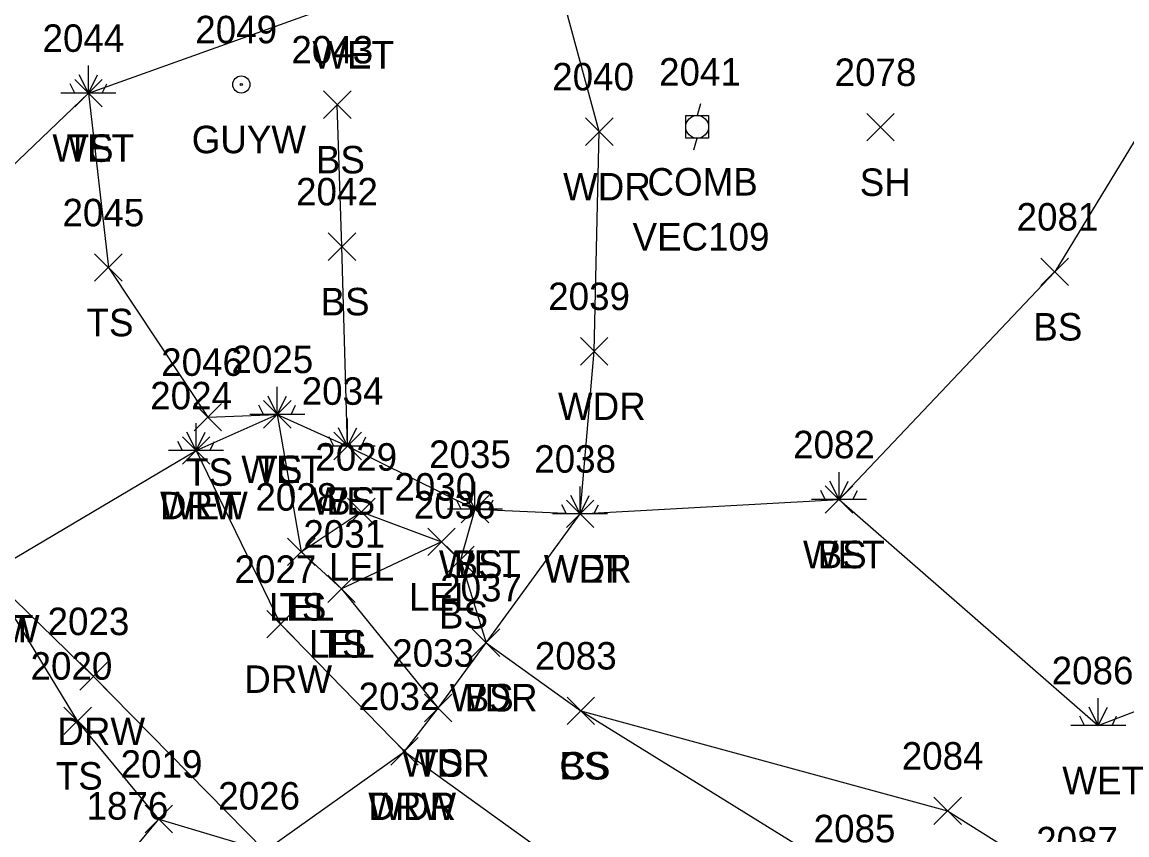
# Model space of a CAD drawing. Extents: x 1512665 to 1513714, y 110636 to 112816.
# Drawn here: x 1512834.1 to 1512914.5, y 110931.3 to 110990.4 of the extents above; entities that cross this region are included whole.
import ezdxf

# ---------------------------------------------------------------- set-up
doc = ezdxf.new("R2010")
doc.units = 0
for name, color, linetype in [('L_A', 7, 'Continuous'), ('L_I', 7, 'Continuous'), ('L_TIC', 7, 'Continuous'), ('LARO', 7, 'Continuous'), ('LAWA', 7, 'Continuous'), ('LELB', 7, 'Continuous'), ('LWET', 7, 'Continuous'), ('R_A', 7, 'Continuous'), ('R_I', 7, 'Continuous'), ('R_TIC', 7, 'Continuous'), ('RDW', 7, 'Continuous'), ('U_A', 7, 'Continuous'), ('U_C', 7, 'Continuous'), ('U_I', 7, 'Continuous'), ('UP', 7, 'Continuous'), ('UPGW', 7, 'Continuous')]:
    doc.layers.add(name, color=color, linetype=linetype)

msp = doc.modelspace()

# ---------------------------------------------------------------- linework, layer by layer
at = {"layer": 'L_TIC'}
for points in [[(1512837.974, 110984.231), (1512839.974, 110986.231)], [(1512839.974, 110984.231), (1512837.974, 110986.231)], [(1512856.074, 110983.389), (1512858.074, 110985.389)], [(1512858.074, 110983.389), (1512856.074, 110985.389)], [(1512875.134, 110981.426), (1512877.134, 110983.426)], [(1512877.134, 110981.426), (1512875.134, 110983.426)], [(1512895.59, 110981.748), (1512897.59, 110983.748)], [(1512897.59, 110981.748), (1512895.59, 110983.748)], [(1512856.414, 110973.06), (1512858.414, 110975.06)], [(1512858.414, 110973.06), (1512856.414, 110975.06)], [(1512839.423, 110971.538), (1512841.423, 110973.538)], [(1512841.423, 110971.538), (1512839.423, 110973.538)], [(1512908.261, 110971.229), (1512910.261, 110973.229)], [(1512910.261, 110971.229), (1512908.261, 110973.229)], [(1512874.763, 110965.444), (1512876.763, 110967.444)], [(1512876.763, 110965.444), (1512874.763, 110967.444)], [(1512846.659, 110960.657), (1512848.659, 110962.657)], [(1512848.659, 110960.657), (1512846.659, 110962.657)], [(1512851.714, 110960.858), (1512853.714, 110962.858)], [(1512853.714, 110960.858), (1512851.714, 110962.858)], [(1512856.825, 110958.552), (1512858.825, 110960.552)], [(1512858.825, 110958.552), (1512856.825, 110960.552)], [(1512892.574, 110954.661), (1512894.574, 110956.661)], [(1512894.574, 110954.661), (1512892.574, 110956.661)], [(1512857.822, 110953.761), (1512859.822, 110955.761)], [(1512859.822, 110953.761), (1512857.822, 110955.761)], [(1512866.091, 110953.959), (1512868.091, 110955.959)], [(1512868.091, 110953.959), (1512866.091, 110955.959)], [(1512873.74, 110953.614), (1512875.74, 110955.614)], [(1512875.74, 110953.614), (1512873.74, 110955.614)], [(1512863.653, 110951.582), (1512865.653, 110953.582)], [(1512865.653, 110951.582), (1512863.653, 110953.582)], [(1512853.458, 110950.85), (1512855.458, 110952.85)], [(1512855.458, 110950.85), (1512853.458, 110952.85)], [(1512853.458, 110950.85), (1512855.458, 110952.85)], [(1512855.458, 110950.85), (1512853.458, 110952.85)], [(1512865.028, 110950.273), (1512867.028, 110952.273)], [(1512867.028, 110950.273), (1512865.028, 110952.273)], [(1512856.381, 110948.159), (1512858.381, 110950.159)], [(1512858.381, 110948.159), (1512856.381, 110950.159)], [(1512856.381, 110948.159), (1512858.381, 110950.159)], [(1512858.381, 110948.159), (1512856.381, 110950.159)], [(1512866.897, 110944.243), (1512868.897, 110946.243)], [(1512868.897, 110944.243), (1512866.897, 110946.243)], [(1512866.897, 110944.243), (1512868.897, 110946.243)], [(1512868.897, 110944.243), (1512866.897, 110946.243)], [(1512863.411, 110939.492), (1512865.411, 110941.492)], [(1512865.411, 110939.492), (1512863.411, 110941.492)], [(1512863.411, 110939.492), (1512865.411, 110941.492)], [(1512865.411, 110939.492), (1512863.411, 110941.492)], [(1512873.787, 110939.291), (1512875.787, 110941.291)], [(1512875.787, 110939.291), (1512873.787, 110941.291)], [(1512873.787, 110939.291), (1512875.787, 110941.291)], [(1512875.787, 110939.291), (1512873.787, 110941.291)], [(1512837.189, 110938.553), (1512839.189, 110940.553)], [(1512839.189, 110938.553), (1512837.189, 110940.553)], [(1512860.965, 110936.336), (1512862.965, 110938.336)], [(1512862.965, 110936.336), (1512860.965, 110938.336)], [(1512900.473, 110932.009), (1512902.473, 110934.009)], [(1512902.473, 110932.009), (1512900.473, 110934.009)], [(1512843.095, 110931.413), (1512845.095, 110933.413)], [(1512845.095, 110931.413), (1512843.095, 110933.413)], [(1512843.095, 110931.413), (1512845.095, 110933.413)], [(1512845.095, 110931.413), (1512843.095, 110933.413)]]:
    msp.add_lwpolyline(points, dxfattribs=at)
at = {"layer": 'LARO'}
msp.add_lwpolyline([(1512854.458, 110951.85), (1512858.822, 110954.761), (1512864.653, 110952.582), (1512857.381, 110949.159)], dxfattribs=at)
at = {"layer": 'LAWA'}
msp.add_lwpolyline([(1512760.327, 110918.9), (1512772.715, 110925.351), (1512775.007, 110936.434), (1512792.554, 110938.683), (1512803.23, 110932.988), (1512815.948, 110931.191), (1512841.584, 110929.37), (1512844.095, 110932.413), (1512851.809, 110930.104), (1512861.965, 110937.336), (1512864.411, 110940.492), (1512867.897, 110945.243), (1512874.74, 110954.614), (1512875.763, 110966.444), (1512876.134, 110982.426), (1512872.076, 110997.369), (1512855.488, 111002.566), (1512840.685, 111007.355)], dxfattribs=at)
at = {"layer": 'LELB'}
for points in [[(1512880.997, 111069.891), (1512889.284, 111054.318), (1512904.053, 111034.187), (1512918.024, 111009.828), (1512920.134, 110990.073), (1512909.261, 110972.229), (1512893.574, 110955.661)], [(1512838.974, 110985.231), (1512840.423, 110972.538), (1512847.659, 110961.657)], [(1512857.825, 110959.552), (1512857.414, 110974.06), (1512857.074, 110984.389)], [(1512847.659, 110961.657), (1512852.714, 110961.858)], [(1512852.714, 110961.858), (1512854.458, 110951.85), (1512857.381, 110949.159), (1512864.411, 110940.492)], [(1512867.091, 110954.959), (1512866.028, 110951.273), (1512867.897, 110945.243), (1512874.787, 110940.291), (1512895.063, 110927.72), (1512902.508, 110913.749), (1512928.484, 110897.044), (1512945.574, 110871.654), (1512953.444, 110855.33), (1512967.722, 110840.945), (1512974.771, 110829.535), (1512966.081, 110822.54), (1512959.925, 110816.123)], [(1512844.095, 110932.413), (1512838.189, 110939.553), (1512831.666, 110950.261)], [(1512874.787, 110940.291), (1512901.473, 110933.009), (1512911.254, 110926.844), (1512935.137, 110909.972), (1512951.516, 110893.128), (1512955.624, 110874.23), (1512953.444, 110855.33)]]:
    msp.add_lwpolyline(points, dxfattribs=at)
at = {"layer": 'LWET'}
for p, q in [((1512838.974, 110985.231), (1512838.974, 110987.231)), ((1512837.974, 110985.231), (1512837.641, 110985.897)), ((1512838.974, 110985.231), (1512838.307, 110986.564)), ((1512838.974, 110985.231), (1512839.641, 110986.564)), ((1512839.974, 110985.231), (1512840.307, 110985.897)), ((1512840.974, 110985.231), (1512836.974, 110985.231)), ((1512852.714, 110961.858), (1512852.714, 110963.858)), ((1512851.714, 110961.858), (1512851.38, 110962.524)), ((1512852.714, 110961.858), (1512852.047, 110963.191)), ((1512852.714, 110961.858), (1512853.38, 110963.191)), ((1512853.714, 110961.858), (1512854.047, 110962.524)), ((1512854.714, 110961.858), (1512850.714, 110961.858)), ((1512846.807, 110959.221), (1512846.807, 110961.221)), ((1512857.825, 110959.552), (1512857.825, 110961.552)), ((1512846.807, 110959.221), (1512846.14, 110960.554)), ((1512846.807, 110959.221), (1512847.473, 110960.554)), ((1512856.825, 110959.552), (1512856.492, 110960.219)), ((1512857.825, 110959.552), (1512857.159, 110960.886)), ((1512857.825, 110959.552), (1512858.492, 110960.886)), ((1512858.825, 110959.552), (1512859.159, 110960.219)), ((1512845.807, 110959.221), (1512845.473, 110959.887)), ((1512847.807, 110959.221), (1512848.14, 110959.887)), ((1512859.825, 110959.552), (1512855.825, 110959.552)), ((1512848.807, 110959.221), (1512844.807, 110959.221)), ((1512867.091, 110954.959), (1512867.091, 110956.959)), ((1512893.574, 110955.661), (1512892.907, 110956.995)), ((1512893.574, 110955.661), (1512893.574, 110957.661)), ((1512893.574, 110955.661), (1512894.24, 110956.995)), ((1512867.091, 110954.959), (1512866.424, 110956.292)), ((1512867.091, 110954.959), (1512867.757, 110956.292)), ((1512874.74, 110954.614), (1512874.74, 110956.614)), ((1512892.574, 110955.661), (1512892.24, 110956.328)), ((1512894.574, 110955.661), (1512894.907, 110956.328)), ((1512866.091, 110954.959), (1512865.757, 110955.626)), ((1512868.091, 110954.959), (1512868.424, 110955.626)), ((1512874.74, 110954.614), (1512874.074, 110955.948)), ((1512874.74, 110954.614), (1512875.407, 110955.948)), ((1512895.574, 110955.661), (1512891.574, 110955.661)), ((1512869.091, 110954.959), (1512865.091, 110954.959)), ((1512876.74, 110954.614), (1512872.74, 110954.614)), ((1512873.74, 110954.614), (1512873.407, 110955.281)), ((1512875.74, 110954.614), (1512876.074, 110955.281)), ((1512912.432, 110939.219), (1512912.432, 110941.219)), ((1512912.432, 110939.219), (1512911.765, 110940.553)), ((1512912.432, 110939.219), (1512913.099, 110940.553)), ((1512914.432, 110939.219), (1512910.432, 110939.219)), ((1512911.432, 110939.219), (1512911.099, 110939.886)), ((1512913.432, 110939.219), (1512913.765, 110939.886))]:
    msp.add_line(p, q, dxfattribs=at)
for points in [[(1512827.592, 110974.325), (1512838.974, 110985.231), (1512857.888, 110992.021), (1512872.076, 110997.369), (1512896.468, 110995.837), (1512920.134, 110990.073), (1512933.522, 110995.148), (1512956.567, 110999.31), (1512966.081, 111012.924), (1512978.758, 111015.543)], [(1512828.676, 110967.967), (1512826.314, 110951.237), (1512831.666, 110950.261), (1512846.807, 110959.221), (1512852.714, 110961.858), (1512857.825, 110959.552), (1512867.091, 110954.959), (1512874.74, 110954.614), (1512893.574, 110955.661), (1512912.432, 110939.219), (1512933.394, 110947.269), (1512941.465, 110952.585), (1512958.813, 110964.455), (1512973.513, 110967.07), (1512985.654, 110971.062)]]:
    msp.add_lwpolyline(points, dxfattribs=at)
at = {"layer": 'R_TIC'}
for points in [[(1512845.807, 110958.221), (1512847.807, 110960.221)], [(1512847.807, 110958.221), (1512845.807, 110960.221)], [(1512851.941, 110945.592), (1512853.941, 110947.592)], [(1512853.941, 110945.592), (1512851.941, 110947.592)], [(1512838.34, 110941.793), (1512840.34, 110943.793)], [(1512840.34, 110941.793), (1512838.34, 110943.793)], [(1512860.965, 110936.336), (1512862.965, 110938.336)], [(1512862.965, 110936.336), (1512860.965, 110938.336)]]:
    msp.add_lwpolyline(points, dxfattribs=at)
at = {"layer": 'RDW'}
for points in [[(1512846.807, 110959.221), (1512852.941, 110946.592), (1512861.965, 110937.336), (1512883.211, 110922.012), (1512899.968, 110905.165), (1512926.485, 110873.446), (1512935.332, 110863.205), (1512946.848, 110850.628), (1512960.543, 110832.025), (1512963.612, 110826.617), (1512966.081, 110822.54), (1512965.912, 110813.145), (1512965.768, 110809.049), (1512964.105, 110806.986), (1512962.879, 110803.833)], [(1512831.666, 110950.261), (1512839.34, 110942.793), (1512851.809, 110930.104), (1512872.871, 110913.575), (1512891.99, 110892.675), (1512913.156, 110874.506), (1512928.573, 110854.542), (1512938.494, 110838.55), (1512948.315, 110825.655), (1512947.325, 110821.384), (1512945.804, 110819.115), (1512944.462, 110817.212)]]:
    msp.add_lwpolyline(points, dxfattribs=at)
at = {"layer": 'UP'}
for p, q in [((1512883.503, 110984.444), (1512883.253, 110983.61)), ((1512882.42, 110981.944), (1512882.42, 110983.61)), ((1512882.42, 110983.61), (1512884.086, 110983.61)), ((1512884.086, 110983.61), (1512884.086, 110981.944)), ((1512883.253, 110982.777), (1512883.253, 110982.777)), ((1512884.086, 110981.944), (1512882.42, 110981.944)), ((1512883.003, 110981.11), (1512883.253, 110981.944))]:
    msp.add_line(p, q, dxfattribs=at)
msp.add_circle((1512883.253, 110982.777), 0.833, dxfattribs=at)
at = {"layer": 'UPGW'}
for radius in [0.625, 0.0833]:
    msp.add_circle((1512850.093, 110985.856), radius, dxfattribs=at)

# ---------------------------------------------------------------- texts
at = {"layer": 'L_A'}
for s, p in [('WET', (1512855.266, 110987.021)), ('WET', (1512836.352, 110980.231)), ('TS', (1512837.383, 110980.231)), ('BS', (1512855.515, 110979.389)), ('WDR', (1512873.496, 110977.426)), ('SH', (1512895.078, 110977.748)), ('BS', (1512855.855, 110969.06)), ('TS', (1512838.833, 110967.538)), ('BS', (1512907.702, 110967.229)), ('WDR', (1512873.125, 110961.444)), ('TS', (1512846.069, 110956.657)), ('WET', (1512850.092, 110956.858)), ('TS', (1512851.123, 110956.858)), ('WET', (1512844.185, 110954.221)), ('WET', (1512855.203, 110954.552)), ('BS', (1512856.266, 110954.552)), ('WET', (1512890.952, 110950.661)), ('BS', (1512892.015, 110950.661)), ('LEL', (1512856.46, 110949.761)), ('WET', (1512864.469, 110949.959)), ('BS', (1512865.532, 110949.959)), ('WDR', (1512872.103, 110949.614)), ('WET', (1512872.118, 110949.614)), ('TS', (1512852.867, 110946.85)), ('LEL', (1512862.291, 110947.582)), ('LEL', (1512852.095, 110946.85)), ('BS', (1512864.469, 110946.273)), ('WET', (1512829.044, 110945.261)), ('LEL', (1512855.018, 110944.159)), ('TS', (1512855.79, 110944.159)), ('WDR', (1512865.259, 110940.243)), ('BS', (1512866.338, 110940.243)), ('WDR', (1512861.773, 110935.492)), ('TS', (1512862.82, 110935.492)), ('CS', (1512873.228, 110935.291)), ('BS', (1512873.228, 110935.291)), ('TS', (1512836.599, 110934.553)), ('WET', (1512909.81, 110934.219)), ('WDR', (1512859.327, 110932.336))]:
    msp.add_text(s, height=2, dxfattribs=at).set_placement(p)
at = {"layer": 'L_I'}
for s, p in [('2044', (1512835.635, 110988.231)), ('2044', (1512835.635, 110988.231)), ('2043', (1512853.736, 110987.389)), ('2040', (1512872.709, 110985.426)), ('2078', (1512893.251, 110985.748)), ('2042', (1512854.076, 110977.06)), ('2045', (1512837.085, 110975.538)), ('2081', (1512906.489, 110975.229)), ('2039', (1512872.416, 110969.444)), ('2046', (1512844.266, 110964.657)), ('2025', (1512849.375, 110964.858)), ('2025', (1512849.375, 110964.858)), ('2024', (1512843.468, 110962.221)), ('2034', (1512854.487, 110962.552)), ('2034', (1512854.487, 110962.552)), ('2082', (1512890.235, 110958.661)), ('2082', (1512890.235, 110958.661)), ('2029', (1512855.475, 110957.761)), ('2035', (1512863.752, 110957.959)), ('2035', (1512863.752, 110957.959)), ('2038', (1512871.402, 110957.614)), ('2038', (1512871.402, 110957.614)), ('2030', (1512861.228, 110955.582)), ('2028', (1512851.119, 110954.85)), ('2028', (1512851.119, 110954.85)), ('2036', (1512862.634, 110954.273)), ('2031', (1512854.609, 110952.159)), ('2031', (1512854.609, 110952.159)), ('2037', (1512864.558, 110948.243)), ('2037', (1512864.558, 110948.243)), ('2033', (1512861.072, 110943.492)), ('2033', (1512861.072, 110943.492)), ('2083', (1512871.449, 110943.291)), ('2083', (1512871.449, 110943.291)), ('2020', (1512834.764, 110942.553)), ('2086', (1512909.038, 110942.219)), ('2032', (1512858.626, 110940.336)), ('2084', (1512898.134, 110936.009)), ('2019', (1512841.315, 110935.413)), ('2019', (1512841.315, 110935.413)), ('1876', (1512838.836, 110932.37)), ('2026', (1512848.416, 110933.104)), ('2085', (1512891.725, 110930.72)), ('2087', (1512907.915, 110929.844))]:
    msp.add_text(s, height=2, dxfattribs=at).set_placement(p)
at = {"layer": 'R_A'}
for p in [(1512844.177, 110954.221), (1512829.036, 110945.261), (1512850.311, 110941.592), (1512836.71, 110937.793), (1512859.335, 110932.336)]:
    msp.add_text('DRW', height=2, dxfattribs=at).set_placement(p)
at = {"layer": 'R_I'}
for s, p in [('2024', (1512843.468, 110962.221)), ('2027', (1512849.602, 110949.592)), ('2023', (1512836.002, 110945.793)), ('2032', (1512858.626, 110940.336)), ('2026', (1512848.416, 110933.104))]:
    msp.add_text(s, height=2, dxfattribs=at).set_placement(p)
at = {"layer": 'U_A'}
for s, p in [('GUYW', (1512846.487, 110980.856)), ('COMB', (1512879.639, 110977.777))]:
    msp.add_text(s, height=2, dxfattribs=at).set_placement(p)
at = {"layer": 'U_C'}
msp.add_text('VEC109', height=2, dxfattribs=at).set_placement((1512878.552, 110973.777))
at = {"layer": 'U_I'}
for s, p in [('2049', (1512846.747, 110988.856)), ('2041', (1512880.481, 110985.777))]:
    msp.add_text(s, height=2, dxfattribs=at).set_placement(p)

doc.saveas('drawing.dxf')
